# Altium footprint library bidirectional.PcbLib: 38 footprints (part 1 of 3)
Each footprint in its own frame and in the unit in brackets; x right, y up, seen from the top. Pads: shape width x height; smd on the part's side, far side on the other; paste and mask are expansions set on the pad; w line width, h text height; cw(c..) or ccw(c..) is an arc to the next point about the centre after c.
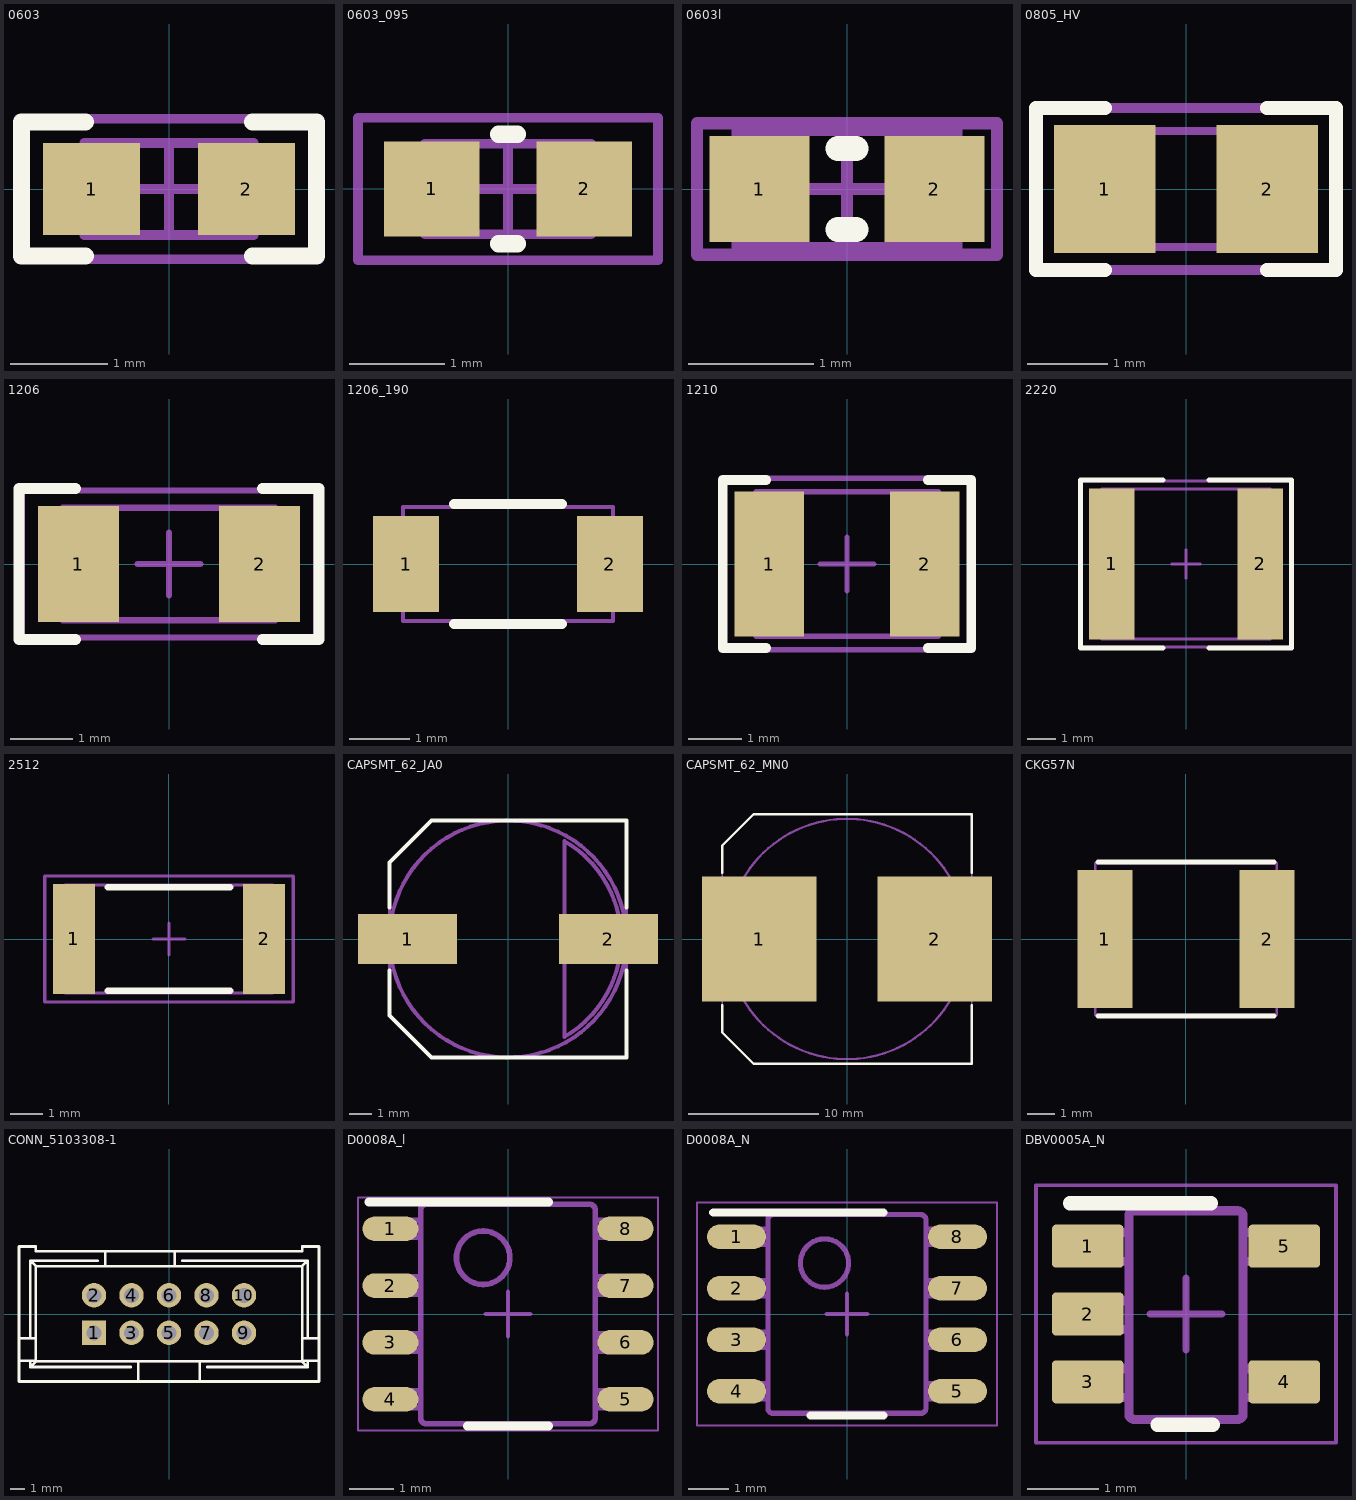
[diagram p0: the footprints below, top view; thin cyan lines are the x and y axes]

## 0603 [mm] "0603 from SM-752 data"
height 0.85
pads (2):
  rect 1x0.95 smd: 1(-0.8,0) 2(0.8,0)
Top Overlay:
  lines w0.178: -0.864,-0.691 -1.524,-0.691 -1.524,0.693 -0.864,0.693 ; 0.864,-0.691 1.524,-0.691 1.524,0.693 0.864,0.693
Mechanical 5:
  lines w0.1: -1.55,-0.725 -1.55,0.725 1.55,0.725 1.55,-0.725 -1.55,-0.725
  text ".Designator" at -1.397,-0.381 h0.76
Mechanical 13:
  lines w0.1: -0.55,-0.475 -0.55,0.475 ; 0.55,-0.475 0.55,0.475 ; -0.875,-0.475 0.875,-0.475 0.875,0.475 -0.875,0.475 -0.875,-0.475
Mechanical 15:
  lines w0.1: -0.475,0 0.475,0 ; 0,-0.475 0,0.475 ; -1.55,-0.725 1.55,-0.725 1.55,0.725 -1.55,0.725 -1.55,-0.725
3D body: height 0.85, standoff 0, extent -0.874,-0.474 -0.551,0.474
3D body: height 0.85, standoff 0, extent -0.549,-0.474 0.549,0.474
3D body: height 0.85, standoff 0, extent 0.551,-0.474 0.874,0.474

## 0603_095 [mm] "0603_095"
height 0.95
pads (2):
  rect 1x1 smd: 1(-0.8,0) 2(0.8,0)
Top Overlay:
  lines w0.18: -0.1,-0.575 0.1,-0.575 ; -0.1,0.575 0.1,0.575
Mechanical 5:
  lines w0.1: -0.875,-0.475 -0.875,0.475 0.875,0.475 0.875,-0.475 -0.875,-0.475
  text ".Designator" at -0.725,-0.2 h0.41
Mechanical 15:
  lines w0.1: -0.475,0 0.475,0 ; 0,-0.475 0,0.475 ; -1.575,-0.75 -1.575,0.75 1.575,0.75 1.575,-0.75 -1.575,-0.75
3D body: height 0.95, standoff 0, extent -0.475,-0.475 0.475,0.475
3D body: height 0.95, standoff 0, extent -0.875,-0.475 -0.475,0.475
3D body: height 0.95, standoff 0, extent 0.475,-0.475 0.875,0.475

## 0603l [mm] "0603 from SM-752 data"
height 0.85
pads (2):
  rect 0.8x0.85 smd: 1(-0.7,0) 2(0.7,0)
Top Overlay:
  lines w0.2: -0.071,-0.325 0.071,-0.325 ; -0.071,0.325 0.071,0.325
Mechanical 5:
  lines w0.1: -1.2,-0.525 1.2,-0.525 1.2,0.525 -1.2,0.525 -1.2,-0.525
  text ".Designator" at -1.05,-0.275 h0.56
Mechanical 13:
  lines w0.1: -0.55,-0.475 -0.55,0.475 ; 0.55,-0.475 0.55,0.475 ; -0.875,-0.475 0.875,-0.475 0.875,0.475 -0.875,0.475 -0.875,-0.475
Mechanical 15:
  lines w0.1: -0.475,0 0.475,0 ; 0,-0.475 0,0.475 ; -1.2,-0.525 -1.2,0.525 1.2,0.525 1.2,-0.525 -1.2,-0.525
3D body: height 0.85, standoff 0, extent -0.874,-0.474 -0.551,0.474
3D body: height 0.85, standoff 0, extent -0.549,-0.474 0.549,0.474
3D body: height 0.85, standoff 0, extent 0.551,-0.474 0.874,0.474

## 0805_HV [mil] "0805 with 30mil clearance between pads"
height 43.31
pads (2):
  rect 50x63 smd: 1(-40,0) 2(40,0)
Top Overlay:
  lines w7: -40,-40 -74,-40 -74,0 -74,40 -40,40 ; 40,-40 74,-40 74,0 74,40 40,40
Mechanical 5:
  lines w5: -74,-40 -74,40 74,40 74,-40 -74,-40
  text ".Designator" at -64,-17 h30
Mechanical 13:
  lines w3.94: -25.59,-28.54 -25.59,28.54 ; 25.59,-28.54 25.59,28.54 ; -43.31,-28.54 43.31,-28.54 43.31,28.54 -43.31,28.54 -43.31,-28.54
3D body: height 43.31, standoff 0, extent -43.29,-28.52 -25.61,28.52
3D body: height 43.31, standoff 0, extent -25.57,-28.52 25.57,28.52
3D body: height 43.31, standoff 0, extent 25.61,-28.52 43.29,28.52

## 1206 [mm] "1206 from SM-752 data"
height 1.35
pads (2):
  rect 1.3x1.85 smd: 1(-1.45,0) 2(1.45,0)
Top Overlay:
  lines w0.178: -1.5,-1.21 -2.4,-1.21 -2.4,1.21 -1.5,1.21 ; 1.5,-1.21 2.4,-1.21 2.4,1.21 1.5,1.21
Mechanical 5:
  lines w0.1: -1.7,-0.9 1.7,-0.9 1.7,0.9 -1.7,0.9 -1.7,-0.9
  text ".Designator" at -1.475,-0.4 h0.81
Mechanical 13:
  lines w0.1: -1.2,-0.9 -1.2,0.9 ; 1.2,-0.9 1.2,0.9 ; -1.7,-0.9 1.7,-0.9 1.7,0.9 -1.7,0.9 -1.7,-0.9
Mechanical 15:
  lines w0.1: -0.5,0 0.5,0 ; 0,-0.5 0,0.5 ; -2.35,-1.175 2.35,-1.175 2.35,1.175 -2.35,1.175 -2.35,-1.175
3D body: height 1.35, standoff 0, extent -1.699,-0.899 -1.201,0.899
3D body: height 1.35, standoff 0, extent -1.199,-0.899 1.199,0.899
3D body: height 1.35, standoff 0, extent 1.201,-0.899 1.699,0.899

## 1206_190 [mm] "1206_190"
height 1.9
pads (2):
  rect 1.1x1.6 smd: 1(-1.7,0) 2(1.7,0)
Top Overlay:
  lines w0.17: -0.9,-1 0.9,-1 ; -0.9,1 0.9,1
Mechanical 5:
  lines w0.07: -1.75,-0.95 1.75,-0.95 1.75,0.95 -1.75,0.95 -1.75,-0.95
  text ".Designator" at -1.5,-0.4 h0.76
3D body: height 1.9, standoff 0, extent -1.749,-0.949 -1.301,0.949
3D body: height 1.9, standoff 0, extent -1.299,-0.949 1.299,0.949
3D body: height 1.9, standoff 0, extent 1.301,-0.949 1.749,0.949

## 1210 [mm] "1210 from SM-752 data"
height 1.35
pads (2):
  rect 1.3x2.7 smd: 1(-1.45,0) 2(1.45,0)
Top Overlay:
  lines w0.178: -1.511,-1.568 -2.316,-1.568 -2.316,1.568 -1.511,1.568 ; 1.511,-1.568 2.316,-1.568 2.316,1.568 1.511,1.568
Mechanical 5:
  lines w0.1: -1.7,-1.35 -1.7,1.35 1.7,1.35 1.7,-1.35 -1.7,-1.35
  text ".Designator" at -1.4,-0.375 h0.76
Mechanical 13:
  lines w0.1: -1.2,-1.35 -1.2,1.35 ; 1.2,-1.35 1.2,1.35 ; -1.7,-1.35 1.7,-1.35 1.7,1.35 -1.7,1.35 -1.7,-1.35
Mechanical 15:
  lines w0.1: -0.5,0 0.5,0 ; 0,-0.5 0,0.5 ; -2.35,-1.6 2.35,-1.6 2.35,1.6 -2.35,1.6 -2.35,-1.6
3D body: height 1.35, standoff 0, extent 1.201,-1.349 1.699,1.349
3D body: height 1.35, standoff 0, extent -1.199,-1.349 1.199,1.349
3D body: height 1.35, standoff 0, extent -1.699,-1.349 -1.201,1.349

## 2220 [mm] "Chip Capacitor, Body 5.7x5.0mm, IPC Medium Density"
height 1.35
pads (2):
  rect 1.6x5.3 smd: 1(-2.6,0) 2(2.6,0)
Top Overlay:
  lines w0.178: -0.811,-2.939 -3.693,-2.939 -3.693,2.939 -0.811,2.939 ; 0.811,-2.939 3.693,-2.939 3.693,2.939 0.811,2.939
Mechanical 5:
  lines w0.1: -2.95,-2.625 -2.95,2.625 2.95,2.625 2.95,-2.625 -2.95,-2.625
  text ".Designator" at -1.875,-0.5 h0.76
Mechanical 13:
  lines w0.1: -2.75,-2.625 -2.75,2.625 ; 2.75,-2.625 2.75,2.625 ; -2.95,-2.625 2.95,-2.625 2.95,2.625 -2.95,2.625 -2.95,-2.625
Mechanical 15:
  lines w0.1: -0.5,0 0.5,0 ; 0,-0.5 0,0.5 ; -3.65,-2.9 3.65,-2.9 3.65,2.9 -3.65,2.9 -3.65,-2.9
3D body: height 1.35, standoff 0, extent 2.751,-2.624 2.949,2.624
3D body: height 1.35, standoff 0, extent -2.749,-2.624 2.749,2.624
3D body: height 1.35, standoff 0, extent -2.949,-2.624 -2.751,2.624

## 2512 [mm] "Chip Resistor, Body 6.3x3.2mm, IPC Medium Density"
height 0.71
pads (2):
  rect 1.3x3.4 smd: 1(-2.95,0) 2(2.95,0)
Top Overlay:
  lines w0.2: -1.9,-1.6 1.9,-1.6 ; -1.9,1.6 1.9,1.6
Mechanical 5:
  lines w0.1: -3.225,-1.675 -3.225,1.675 3.225,1.675 3.225,-1.675 -3.225,-1.675
  text ".Designator" at -1.85,-0.5 h1.02
Mechanical 13:
  lines w0.1: -2.463,-1.675 -2.463,1.675 ; 2.463,-1.675 2.463,1.675 ; -3.225,-1.675 -3.225,1.675 3.225,1.675 3.225,-1.675 -3.225,-1.675
Mechanical 15:
  lines w0.1: -0.5,0 0.5,0 ; 0,-0.5 0,0.5 ; -3.85,-1.95 -3.85,1.95 3.85,1.95 3.85,-1.95 -3.85,-1.95
3D body: height 0.71, standoff 0, extent 2.464,-1.674 3.224,1.674
3D body: height 0.71, standoff 0, extent -2.462,-1.674 2.462,1.674
3D body: height 0.71, standoff 0, extent -3.224,-1.674 -2.464,1.674

## CAPSMT_62_JA0 [mm] "10 x 10mm:  Chemi-Con JA0"
height 10.5
pads (2):
  rect 4.4x2.2 smd: 1(-4.45,0) 2(4.45,0)
Top Overlay:
  lines w0.178: -5.25,-1.4 -5.25,-3.4 -3.4,-5.25 0,-5.25 5.25,-5.25 5.25,-1.4 ; -5.25,1.4 -5.25,3.4 -3.4,5.25 0,5.25 5.25,5.25 5.25,1.4
Mechanical 5:
  lines w0.127: -5.25,-3.4 -5.25,3.4 -3.4,5.25 0,5.25 5.25,5.25 5.25,-5.25 0,-5.25 -3.4,-5.25 -5.25,-3.4
  text ".Designator" at -1.524,-0.508 h0.76
Mechanical 13:
  circle w0.178: c0,0 r5.25
  lines w0.178: 2.505,-4.339 ccw(c0,0) 2.505,4.339 2.505,-4.339
3D body: height 1, standoff 0, extent -5.251,-5.251 5.251,5.251
3D body: height 10.5, standoff 1, extent -5.261,-5.261 5.261,5.261
3D body: height 10.5, standoff 10.4, extent 2.505,-4.349 5.022,4.349

## CAPSMT_62_MN0 [mm] "18 x 21.5mm:  Chemi-Con MN0"
height 22
pads (2):
  rect 8.8x9.6 smd: 1(-6.75,0) 2(6.75,0)
Top Overlay:
  lines w0.178: -9.6,-5.1 -9.6,-7.2 -7.2,-9.6 0,-9.6 9.6,-9.6 9.6,-5.1 ; -9.6,5.1 -9.6,7.2 -7.2,9.6 0,9.6 9.6,9.6 9.6,5.1
Mechanical 5:
  lines w0.127: -9.6,-7.2 -7.2,-9.6 0,-9.6 9.6,-9.6 9.6,9.6 0,9.6 -7.2,9.6 -9.6,7.2 -9.6,-7.2
  text ".Designator" at -1.524,-0.508 h0.76
Mechanical 13:
  circle w0.178: c0,0 r9.25
  lines w0.178: 4,-2 6,-2 6,2 4,2 4,-2
3D body: height 22, standoff 21.9, extent 4.001,-1.999 5.999,1.999
3D body: height 22, standoff 2, extent -9.261,-9.261 9.261,9.261
3D body: height 2, standoff 0, extent -9.601,-9.601 9.601,9.601

## CKG57N [mm] "Chip Capacitor, Body 6.0x5.0x5.0mm,"
height 5.5
pads (2):
  rect 2x5 smd: 1(-2.95,0) 2(2.95,0)
Top Overlay:
  lines w0.18: -3.2,-2.8 3.2,-2.8 ; -3.2,2.8 3.2,2.8
Mechanical 5:
  lines w0.1: -3.3,-2.75 3.3,-2.75 3.3,2.75 -3.3,2.75 -3.3,-2.75
  text ".Designator" at -1.8,-0.5 h0.76
3D body: height 1, standoff 0, extent 3.101,-2.749 3.299,2.749
3D body: height 1, standoff 0, extent -3.299,-2.749 -3.101,2.749
3D body: height 5.5, standoff 1, extent -2.199,-2.749 2.199,2.749
3D body: height 5.5, standoff 1, extent 2.201,-2.749 3.299,2.749
3D body: height 5.5, standoff 1, extent -3.299,-2.749 -2.201,2.749
3D body: height 0.3, standoff 0, extent -3.299,-2.749 -1.701,2.749
3D body: height 0.3, standoff 0, extent 1.701,-2.749 3.299,2.749
3D body: height 5.5, standoff 1, extent -3.299,-2.749 -3.101,2.749

## CONN_5103308-1 [mm] "TE Connectivity (AMP) Rev E datasheet"
height 9.982
pads (10):
  rect 1.65x1.65 hole 1.016 mask+0: 1(-5.08,-1.27)
  round 1.65 hole 1.016 mask+0: 2(-5.08,1.27) 3(-2.54,-1.27) 4(-2.54,1.27) 5(0,-1.27) 6(0,1.27) 7(2.54,-1.27) 8(2.54,1.27) 9(5.08,-1.27) 10(5.08,1.27)
Top Overlay:
  lines w0.178: -4.826,3.619 -9.398,3.619 ; -2.603,-3.594 -9.398,-3.594 ; 0.889,3.619 9.398,3.619 ; 2.603,-3.594 9.398,-3.594 ; -10.16,-3.175 -9.398,-3.175 ; -10.16,-3.175 -10.16,-1.651 ; -10.16,-3.175 -10.16,-4.572 -2.603,-4.572 -2.095,-4.572 ; -10.16,-1.651 -9.398,-1.651 ; -10.16,-1.651 -10.16,4.572 -9.017,4.572 -9.017,4.255 -4.826,4.255 -4.318,4.255 ; -9.398,-3.594 -9.398,-3.175 ; -9.398,-3.594 -9.017,-3.213 ; -9.398,-3.175 -9.017,-3.175 ; -9.398,-1.651 -9.017,-1.651 ; -9.398,-1.651 -9.398,3.619 ; -9.398,3.619 -9.017,3.238 ; -9.017,-3.213 -2.112,-3.213 -2.095,-3.213 ; -9.017,-3.213 -9.017,-3.175 ; -9.017,-3.175 -9.017,-1.651 ; -9.017,-1.651 -9.017,3.238 ; -9.017,3.238 -4.334,3.238 -4.318,3.238 ; -4.318,3.238 -4.318,4.255 ; -4.318,3.238 0.381,3.238 ; -4.318,4.255 -3.556,4.255 -0.381,4.255 0.381,4.255 ; -2.095,-4.572 -2.095,-3.213 ; -2.095,-4.572 -1.333,-4.572 1.333,-4.572 2.095,-4.572 ; -2.095,-3.213 2.095,-3.213 ; 0.381,3.238 0.397,3.238 9.017,3.238 ; 0.381,3.238 0.381,4.255 ; 0.381,4.255 0.889,4.255 9.017,4.255 9.017,4.572 10.16,4.572 10.16,-1.651 ; 2.095,-4.572 2.095,-3.213 ; 2.095,-4.572 2.603,-4.572 10.16,-4.572 10.16,-3.175 ; 2.095,-3.213 2.112,-3.213 9.017,-3.213 ; 9.017,-3.213 9.017,-3.175 ; 9.017,-3.213 9.398,-3.594 ; 9.017,-3.175 9.398,-3.175 ; 9.017,-3.175 9.017,-1.651 ; 9.017,-1.651 9.398,-1.651 ; 9.017,-1.651 9.017,3.238 ; 9.017,3.238 9.398,3.619 ; 9.398,-3.594 9.398,-3.175 ; 9.398,-3.175 10.16,-3.175 ; 9.398,-1.651 9.398,3.619 ; 9.398,-1.651 10.16,-1.651 ; 10.16,-3.175 10.16,-1.651
Mechanical 5:
  rectangle: -5.588,-1.778 -4.572,-0.762
  lines w0.127: -4.826,3.619 -9.398,3.619 ; -2.603,-3.594 -9.398,-3.594 ; 0.889,3.619 9.398,3.619 ; 2.603,-3.594 9.398,-3.594 ; -10.16,-3.175 -10.16,-4.572 -2.603,-4.572 -2.095,-4.572 ; -10.16,-3.175 -10.16,-1.651 ; -10.16,-3.175 -9.398,-3.175 ; -10.16,-1.651 -10.16,4.572 -9.017,4.572 -9.017,4.255 -4.826,4.255 -4.318,4.255 ; -10.16,-1.651 -9.398,-1.651 ; -9.398,-3.594 -9.017,-3.213 ; -9.398,-3.594 -9.398,-3.175 ; -9.398,-3.175 -9.017,-3.175 ; -9.398,-1.651 -9.398,3.619 ; -9.398,-1.651 -9.017,-1.651 ; -9.398,3.619 -9.017,3.238 ; -9.017,-3.213 -9.017,-3.175 ; -9.017,-3.213 -2.112,-3.213 -2.095,-3.213 ; -9.017,-3.175 -9.017,-1.651 ; -9.017,-1.651 -9.017,3.238 ; -9.017,3.238 -4.334,3.238 -4.318,3.238 ; -4.318,3.238 0.381,3.238 ; -4.318,3.238 -4.318,4.255 ; -4.318,4.255 -3.556,4.255 -0.381,4.255 0.381,4.255 ; -2.095,-4.572 -1.333,-4.572 1.333,-4.572 2.095,-4.572 ; -2.095,-4.572 -2.095,-3.213 ; -2.095,-3.213 2.095,-3.213 ; 0.381,3.238 0.381,4.255 ; 0.381,3.238 0.397,3.238 9.017,3.238 ; 0.381,4.255 0.889,4.255 9.017,4.255 9.017,4.572 10.16,4.572 10.16,-1.651 ; 2.095,-4.572 2.603,-4.572 10.16,-4.572 10.16,-3.175 ; 2.095,-4.572 2.095,-3.213 ; 2.095,-3.213 2.112,-3.213 9.017,-3.213 ; 9.017,-3.213 9.398,-3.594 ; 9.017,-3.213 9.017,-3.175 ; 9.017,-3.175 9.017,-1.651 ; 9.017,-3.175 9.398,-3.175 ; 9.017,-1.651 9.017,3.238 ; 9.017,-1.651 9.398,-1.651 ; 9.017,3.238 9.398,3.619 ; 9.398,-3.594 9.398,-3.175 ; 9.398,-3.175 10.16,-3.175 ; 9.398,-1.651 10.16,-1.651 ; 9.398,-1.651 9.398,3.619 ; 10.16,-3.175 10.16,-1.651 ; -5.391,-1.581 -5.391,-0.959 -4.769,-0.959 -4.769,-1.581 -5.391,-1.581
  text ".Designator" at -1.524,-0.508 h0.76
3D body: height 9.87, standoff -3.03, extent -10.16,-4.572 10.16,4.572

## D0008A_l [mm] "SOIC, 8-Leads, Body 4.9x3.9mm, Pitch 1.27mm, IPC High Density"
height 1.75
pads (8):
  oval 1.25x0.55 smd: 1(-2.625,1.905) 2(-2.625,0.635) 3(-2.625,-0.635) 4(-2.625,-1.905) 5(2.625,-1.905) 6(2.625,-0.635) 7(2.625,0.635) 8(2.625,1.905)
Top Overlay:
  lines w0.2: -3.1,2.5 0.9,2.5 ; -0.9,-2.5 0.9,-2.5
Mechanical 5:
  lines w0.127: -2.375,-2.095 -2.375,-1.715 ; -2.375,-2.095 -2.589,-2.095 -3.002,-2.095 -3.002,-1.715 -2.589,-1.715 -2.375,-1.715 ; -2.375,-2.095 -1.995,-2.095 -1.952,-2.095 -1.952,-1.715 -1.995,-1.715 -2.375,-1.715 ; -2.375,-0.825 -2.375,-0.445 ; -2.375,-0.825 -2.589,-0.825 -3.002,-0.825 -3.002,-0.445 -2.589,-0.445 -2.375,-0.445 ; -2.375,-0.825 -1.995,-0.825 -1.952,-0.825 -1.952,-0.445 -1.995,-0.445 -2.375,-0.445 ; -2.375,0.445 -2.375,0.825 ; -2.375,0.445 -2.589,0.445 -3.002,0.445 -3.002,0.825 -2.589,0.825 -2.375,0.825 ; -2.375,0.445 -1.995,0.445 -1.952,0.445 -1.952,0.825 -1.995,0.825 -2.375,0.825 ; -2.375,1.715 -2.375,2.095 ; -2.375,1.715 -2.589,1.715 -3.002,1.715 -3.002,2.095 -2.589,2.095 -2.375,2.095 ; -2.375,1.715 -1.995,1.715 -1.952,1.715 -1.952,2.095 -1.995,2.095 -2.375,2.095 ; -0.332,-2.45 -0.182,-2.45 ; -0.332,-2.45 -0.182,-2.45 ; -0.332,-2.45 -1.825,-2.45 -1.826,-2.45 cw(c-1.825,-2.323) -1.952,-2.324 -1.952,-2.323 -1.952,2.323 -1.952,2.324 cw(c-1.825,2.323) -1.826,2.45 -1.825,2.45 -0.332,2.45 ; -0.332,2.45 -0.182,2.45 ; -0.332,2.45 -0.182,2.45 ; -0.182,-2.45 0.178,-2.45 ; -0.182,2.45 0.178,2.45 ; 0.178,-2.45 0.328,-2.45 ; 0.178,-2.45 0.328,-2.45 ; 0.178,2.45 0.328,2.45 ; 0.178,2.45 0.328,2.45 ; 0.328,-2.45 1.821,-2.45 1.822,-2.45 ccw(c1.821,-2.323) 1.948,-2.324 1.948,-2.323 1.948,2.323 1.948,2.324 ccw(c1.821,2.323) 1.822,2.45 1.821,2.45 0.328,2.45 ; 2.371,-2.095 2.371,-1.715 ; 2.371,-2.095 1.991,-2.095 1.948,-2.095 1.948,-1.715 1.991,-1.715 2.371,-1.715 ; 2.371,-2.095 2.585,-2.095 2.998,-2.095 2.998,-1.715 2.585,-1.715 2.371,-1.715 ; 2.371,-0.825 2.371,-0.445 ; 2.371,-0.825 1.991,-0.825 1.948,-0.825 1.948,-0.445 1.991,-0.445 2.371,-0.445 ; 2.371,-0.825 2.585,-0.825 2.998,-0.825 2.998,-0.445 2.585,-0.445 2.371,-0.445 ; 2.371,0.445 2.371,0.825 ; 2.371,0.445 1.991,0.445 1.948,0.445 1.948,0.825 1.991,0.825 2.371,0.825 ; 2.371,0.445 2.585,0.445 2.998,0.445 2.998,0.825 2.585,0.825 2.371,0.825 ; 2.371,1.715 2.371,2.095 ; 2.371,1.715 1.991,1.715 1.948,1.715 1.948,2.095 1.991,2.095 2.371,2.095 ; 2.371,1.715 2.585,1.715 2.998,1.715 2.998,2.095 2.585,2.095 2.371,2.095 ; -0.555,0.659 ccw(c-0.555,1.256) -0.555,1.853 ccw(c-0.555,1.256) -0.555,0.659
  text ".Designator" at -1.625,-0.625 h0.89
Mechanical 15:
  lines w0.05: -3.35,-2.6 3.35,-2.6 3.35,2.6 -3.35,2.6 -3.35,-2.6
  lines w0.1: -0.5,0 0.5,0 ; 0,-0.5 0,0.5
3D body: height 1.63, standoff 0, extent -3,-2.45 3,2.45

## D0008A_N [mm] "SOIC, 8-Leads, Body 4.9x3.9mm, Pitch 1.27mm, IPC Medium Density"
height 1.75
pads (8):
  oval 1.45x0.6 smd: 1(-2.725,1.905) 2(-2.725,0.635) 3(-2.725,-0.635) 4(-2.725,-1.905) 5(2.725,-1.905) 6(2.725,-0.635) 7(2.725,0.635) 8(2.725,1.905)
Top Overlay:
  lines w0.2: -3.3,2.5 0.9,2.5 ; -0.9,-2.5 0.9,-2.5
Mechanical 5:
  lines w0.127: -2.375,-2.095 -1.995,-2.095 -1.952,-2.095 -1.952,-1.715 -1.995,-1.715 -2.375,-1.715 ; -2.375,-2.095 -2.589,-2.095 -3.002,-2.095 -3.002,-1.715 -2.589,-1.715 -2.375,-1.715 ; -2.375,-2.095 -2.375,-1.715 ; -2.375,-0.825 -1.995,-0.825 -1.952,-0.825 -1.952,-0.445 -1.995,-0.445 -2.375,-0.445 ; -2.375,-0.825 -2.589,-0.825 -3.002,-0.825 -3.002,-0.445 -2.589,-0.445 -2.375,-0.445 ; -2.375,-0.825 -2.375,-0.445 ; -2.375,0.445 -1.995,0.445 -1.952,0.445 -1.952,0.825 -1.995,0.825 -2.375,0.825 ; -2.375,0.445 -2.589,0.445 -3.002,0.445 -3.002,0.825 -2.589,0.825 -2.375,0.825 ; -2.375,0.445 -2.375,0.825 ; -2.375,1.715 -1.995,1.715 -1.952,1.715 -1.952,2.095 -1.995,2.095 -2.375,2.095 ; -2.375,1.715 -2.589,1.715 -3.002,1.715 -3.002,2.095 -2.589,2.095 -2.375,2.095 ; -2.375,1.715 -2.375,2.095 ; -0.332,-2.45 -1.825,-2.45 -1.826,-2.45 cw(c-1.825,-2.323) -1.952,-2.324 -1.952,-2.323 -1.952,2.323 -1.952,2.324 cw(c-1.825,2.323) -1.826,2.45 -1.825,2.45 -0.332,2.45 ; -0.332,-2.45 -0.182,-2.45 ; -0.332,-2.45 -0.182,-2.45 ; -0.332,2.45 -0.182,2.45 ; -0.332,2.45 -0.182,2.45 ; -0.182,-2.45 0.178,-2.45 ; -0.182,2.45 0.178,2.45 ; 0.178,-2.45 0.328,-2.45 ; 0.178,-2.45 0.328,-2.45 ; 0.178,2.45 0.328,2.45 ; 0.178,2.45 0.328,2.45 ; 0.328,-2.45 1.821,-2.45 1.822,-2.45 ccw(c1.821,-2.323) 1.948,-2.324 1.948,-2.323 1.948,2.323 1.948,2.324 ccw(c1.821,2.323) 1.822,2.45 1.821,2.45 0.328,2.45 ; 2.371,-2.095 2.585,-2.095 2.998,-2.095 2.998,-1.715 2.585,-1.715 2.371,-1.715 ; 2.371,-2.095 1.991,-2.095 1.948,-2.095 1.948,-1.715 1.991,-1.715 2.371,-1.715 ; 2.371,-2.095 2.371,-1.715 ; 2.371,-0.825 2.585,-0.825 2.998,-0.825 2.998,-0.445 2.585,-0.445 2.371,-0.445 ; 2.371,-0.825 1.991,-0.825 1.948,-0.825 1.948,-0.445 1.991,-0.445 2.371,-0.445 ; 2.371,-0.825 2.371,-0.445 ; 2.371,0.445 2.585,0.445 2.998,0.445 2.998,0.825 2.585,0.825 2.371,0.825 ; 2.371,0.445 1.991,0.445 1.948,0.445 1.948,0.825 1.991,0.825 2.371,0.825 ; 2.371,0.445 2.371,0.825 ; 2.371,1.715 2.585,1.715 2.998,1.715 2.998,2.095 2.585,2.095 2.371,2.095 ; 2.371,1.715 1.991,1.715 1.948,1.715 1.948,2.095 1.991,2.095 2.371,2.095 ; 2.371,1.715 2.371,2.095 ; -0.555,0.659 cw(c-0.555,1.256) -0.555,1.853 cw(c-0.555,1.256) -0.555,0.659
  text ".Designator" at -1.625,-0.625 h0.89
Mechanical 15:
  lines w0.05: -3.7,-2.75 3.7,-2.75 3.7,2.75 -3.7,2.75 -3.7,-2.75
  lines w0.1: -0.5,0 0.5,0 ; 0,-0.5 0,0.5
3D body: height 1.63, standoff 0, extent -3,-2.45 3,2.45

## DBV0005A_N [mm] "SOT23, 5-Leads, Body 2.9x1.6mm, Pitch 0.95mm, Lead Span 2.8mm, IPC Medium Density"
height 1.45
pads (5):
  rrect17% 1x0.6 smd: 1(-1.375,0.95) 2(-1.375,0) 3(-1.375,-0.95) 4(1.375,-0.95) 5(1.375,0.95)
Top Overlay:
  lines w0.2: -1.625,1.55 0.35,1.55 ; -0.4,-1.55 0.375,-1.55
Mechanical 5:
  lines w0.127: -0.801,1.371 cw(c-0.725,1.37) -0.725,1.446 ; -0.801,1.37 -0.801,1.371 ; -0.801,1.37 -0.801,-1.399 -0.801,-1.4 ccw(c-0.725,-1.399) -0.725,-1.475 ; -0.725,-1.475 0.723,-1.475 0.724,-1.475 ccw(c0.723,-1.399) 0.799,-1.4 0.799,-1.399 0.799,1.37 ; -0.725,-1.475 -0.725,-1.475 ; -0.725,1.446 -0.725,1.446 ; -0.725,1.446 0.723,1.446 0.724,1.446 cw(c0.723,1.37) 0.799,1.371 ; 0.799,1.37 0.799,1.371 ; -1.423,-1.167 -1.423,-0.767 -1.199,-0.767 -1.105,-0.767 -1.088,-0.767 -0.835,-0.767 -0.801,-0.767 -0.801,-1.167 -0.835,-1.167 -1.088,-1.167 -1.105,-1.167 -1.199,-1.167 -1.423,-1.167 ; -1.423,-0.215 -1.423,0.186 -1.199,0.186 -1.105,0.186 -1.088,0.186 -0.835,0.186 -0.801,0.186 -0.801,-0.215 -0.835,-0.215 -1.088,-0.215 -1.105,-0.215 -1.199,-0.215 -1.423,-0.215 ; -1.423,0.738 -1.423,1.138 -1.199,1.138 -1.105,1.138 -1.088,1.138 -0.835,1.138 -0.801,1.138 -0.801,0.738 -0.835,0.738 -1.088,0.738 -1.105,0.738 -1.199,0.738 -1.423,0.738 ; 0.799,-1.167 0.834,-1.167 1.087,-1.167 1.103,-1.167 1.198,-1.167 1.422,-1.167 1.422,-0.767 1.198,-0.767 1.103,-0.767 1.087,-0.767 0.834,-0.767 0.799,-0.767 0.799,-1.167 ; 0.799,0.738 0.834,0.738 1.087,0.738 1.103,0.738 1.198,0.738 1.422,0.738 1.422,1.138 1.198,1.138 1.103,1.138 1.087,1.138 0.834,1.138 0.799,1.138 0.799,0.738
  text ".Designator" at -0.25,0.95 h0.51
Mechanical 15:
  lines w0.05: -2.1,-1.8 -2.1,1.8 2.1,1.8 2.1,-1.8 -2.1,-1.8
  lines w0.1: -0.5,0 0.5,0 ; 0,-0.5 0,0.5
3D body: height 1.09, standoff 0, extent -1.422,-1.461 1.423,1.46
